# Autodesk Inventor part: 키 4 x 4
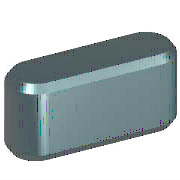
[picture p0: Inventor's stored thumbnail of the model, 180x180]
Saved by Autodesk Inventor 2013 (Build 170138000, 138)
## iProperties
IsCustomPart: 0
Created: 2009-02
Part Number: 키 4 x 4
Material: 강철, 연강
Description: 키 및 해당 키홈
Document SubType Name: Modeling
Standard: KS B 1311
Designer: KYOUNG IL JANG
Standards Organization: KS
Language: ko-KR
Size Designation: 4 x 4 x 12
Categories: <MemberInstance><Categories><Category DisplayName="샤프트 부품" InternalName="7f7aeb1f-a693-4053-b835-cee3144e0d98" Mnemonic="SHFT"><Category DisplayName="키" Interna
Density: 7.86 g/cm^3
Mass: 1.38739 g
Surface Area: 1.94869 cm^2
Volume: 0.176513 cm^3
Author: KYOUNG IL JANG
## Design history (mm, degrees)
workplane "Work Plane1"
workplane "Work Plane2"
sketch "스케치1"
  geometry: L1 (2, 2)-(10, 2); L2 (10, -2)-(2, -2); L3 (0, 9.4)-(0, -7.4) reference; L4 (-5, 0)-(30, 0) reference; L5 (12, 0)-(12, 7); A1 r 2 centre (2, 0) between (2, 2) and (2, -2); A2 r 2 centre (10, 0) between (10, -2) and (10, 2)
  constraints: 6 end point, 5 point on circle, 4 tangent, 3 point on line, 2 centre point, 1 horizontal, 1 parallel, 1 perpendicular
  dimensions: "d0" = 2 radius of A1 (= 0.5 x PB); "d13" = 2 radius of A2 (= 0.5 x PB); "d14" = 12 distance between parallel lines of L5 L3 (= NLG)
extrude "본체1" new body sketch "스케치1" taper "d3" = 0 deg; stored distance "d4" = 10
workplane "Work Plane3"
body "Solid1"
chamfer "모따기1" distance "d8" = 0.25 (= PHH); stored, may be unused: second distance "d9" = 0.25 (= PHH), angle "d15" = 45 deg
other parameters: "d1" = -2.5 (= -PNT), "d2" = 1.5 (= PH - PNT), "NLG" = 12 [user parameter; used in 3 equation terms], "PB" = 4 [user parameter; used in 2 equation terms], "PNT" = 2.5 [user parameter; used in 2 equation terms], "PH" = 4 [user parameter; used in 1 equation term], "PHH" = 0.25 [user parameter; used in 2 equation terms], "d10" = 0, "d16" = 0, "d17" = 0, "d18" = 0, "PLB2" = 12 (= NLG) [user parameter], "WDMAX" = 12 [user parameter], "PLB1" = 12 (= NLG) [user parameter], "RR" = 0.08 [user parameter], "PUEB" = 1.8 [user parameter]
